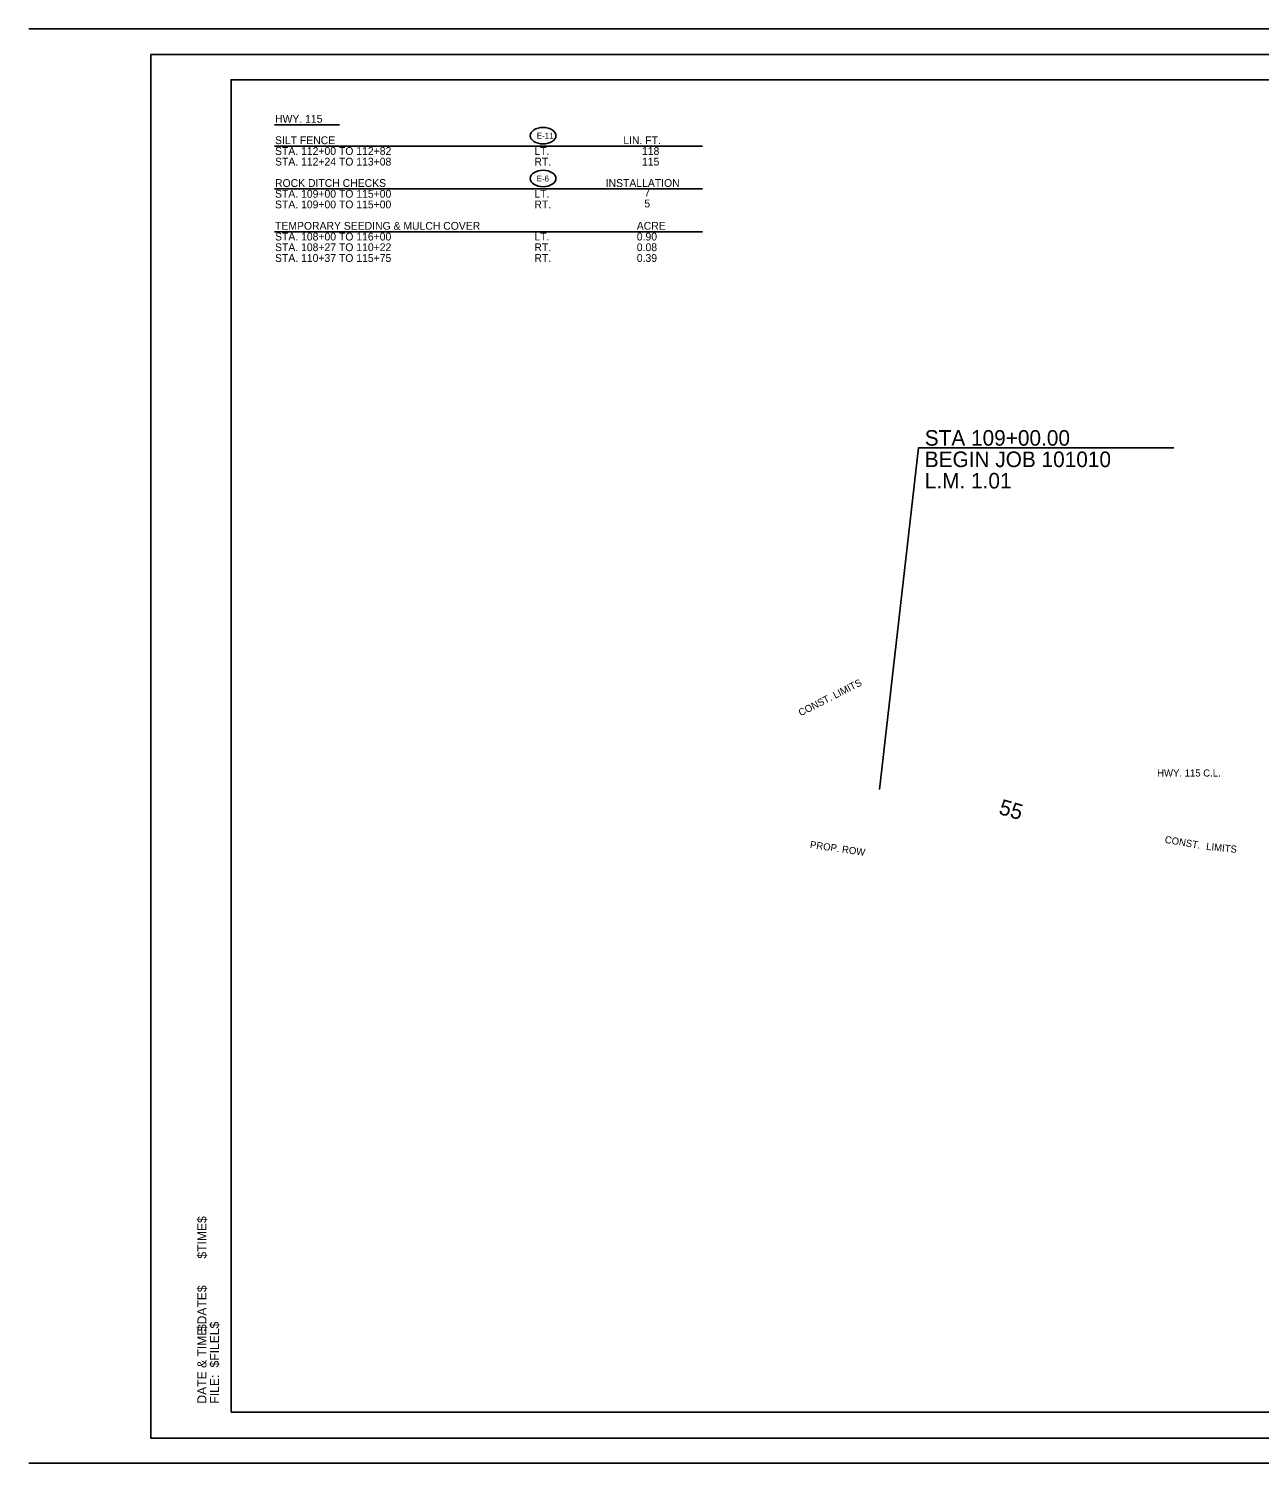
# Model space of a CAD drawing. Extents: x 9844 to 14104, y 9961 to 11067.
# Drawn here: x 9844 to 10793, y 9961 to 11067 of the extents above; entities that cross this region are included whole.
import ezdxf

# ---------------------------------------------------------------- set-up
doc = ezdxf.new("R2010")
doc.units = 0
for name, color, linetype in [('Default', 7, 'Continuous'), ('R_Border', 7, 'Continuous'), ('R_Detour Annot', 7, 'Continuous'), ('R_Erosion', 7, 'Continuous'), ('R_No Plot', 7, 'Continuous'), ('R_NoPlot', 7, 'Continuous'), ('R_Proposed Const Limits Annot', 7, 'Continuous'), ('R_ROW Annot Labels Ends', 7, 'Continuous'), ('STA Text', 7, 'Continuous'), ('TEXT', 7, 'Continuous')]:
    doc.layers.add(name, color=color, linetype=linetype)

msp = doc.modelspace()

# ---------------------------------------------------------------- linework, layer by layer
at = {"layer": 'R_Border'}
for p, q in [((11603.9, 11066.7), (9843.9, 11066.7)), ((10000, 11027.3), (11580.9, 11027.3)), ((10000, 10000), (10000, 11027.3)), ((10762.6, 11026), (10762.6, 11026)), ((10762.6, 11026), (10762.6, 11026)), ((11580.9, 10000), (10000, 10000)), ((9843.9, 9960.6), (11603.9, 9960.6))]:
    msp.add_line(p, q, dxfattribs=at)
at = {"layer": 'R_Erosion'}
for p, q in [((10033.6, 10992.7), (10083.6, 10992.7)), ((10033.6, 10976.2), (10363.6, 10976.2)), ((10033.6, 10943.2), (10363.6, 10943.2)), ((10033.6, 10910.2), (10363.6, 10910.2))]:
    msp.add_line(p, q, dxfattribs=at)
for centre in [(10240.6, 10984.2), (10240.6, 10951.2)]:
    msp.add_ellipse(centre, major_axis=(9.94, 0), ratio=0.638788, dxfattribs=at)
at = {"layer": 'R_No Plot'}
msp.add_lwpolyline([(10000, 10000), (11580.9, 10000), (11580.3, 10963.3), (11365.4, 10963.3), (11357.3, 10959.9), (11348.5, 10961.4), (11348.3, 10977.9), (11169.6, 10977.9), (11169.6, 11027.3), (10000, 11027.3)], close=True, dxfattribs=at)
msp.add_lwpolyline([(10000, 10000), (11580.9, 10000), (11580.3, 10963.3), (11365.4, 10963.3), (11357.3, 10959.9), (11348.5, 10961.4), (11348.3, 10977.9), (11169.6, 10977.9), (11169.6, 11027.3), (10000, 11027.3)], close=True, dxfattribs=at)
at = {"layer": 'R_NoPlot'}
msp.add_lwpolyline([(9938, 11046.8), (11604.7, 11046.8), (11604.7, 9980.1), (9938, 9980.1)], close=True, dxfattribs=at)
at = {"layer": 'STA Text'}
msp.add_lwpolyline([(10727.2, 10743.6), (10530.2, 10743.6), (10500, 10480)], dxfattribs=at)

# ---------------------------------------------------------------- texts
at = {"layer": 'Default'}
for s, height, p in [('$TIME$', 6.98, (9981, 10118.4)), ('$DATE$', 6.98, (9981, 10062.5)), ('DATE & TIME:', 6.984, (9981, 10006.6)), ('$FILEL$', 6.98, (9990.6, 10034.5)), ('FILE: ', 6.98, (9990.6, 10006.6))]:
    msp.add_text(s, height=height, rotation=90, dxfattribs=at).set_placement(p)
at = {"layer": 'R_Detour Annot'}
msp.add_text('55', height=12, rotation=343.9098, dxfattribs=at).set_placement((10591.4, 10461.4))
at = {"layer": 'R_Erosion'}
for s, height, p in [('HWY. 115', 6, (10033.9, 10994.2)), ('SILT FENCE', 6, (10033.9, 10977.7)), ('E-11', 4.54, (10235.8, 10981.9)), ('LIN. FT.', 6, (10302.5, 10977.7)), ('STA. 112+00 TO 112+82', 6, (10033.9, 10969.4)), ('LT.', 6, (10233.9, 10969.4)), ('118', 6, (10316.9, 10969.4)), ('STA. 112+24 TO 113+08', 6, (10033.9, 10961.2)), ('RT.', 6, (10233.9, 10961.2)), ('115', 6, (10316.9, 10961.2)), ('ROCK DITCH CHECKS   ', 6, (10033.9, 10944.7)), ('INSTALLATION', 6, (10288.9, 10944.7)), ('STA. 109+00 TO 115+00', 6, (10033.9, 10936.4)), ('LT.', 6, (10233.9, 10936.4)), ('7', 6, (10318.7, 10937.2)), ('STA. 109+00 TO 115+00', 6, (10033.9, 10928.2)), ('RT.', 6, (10233.9, 10928.2)), ('5', 6, (10318.7, 10928.9)), ('TEMPORARY SEEDING & MULCH COVER', 6, (10033.9, 10911.7)), ('ACRE', 6, (10312.9, 10911.7)), ('STA. 108+00 TO 116+00', 6, (10033.9, 10903.4)), ('LT.', 6, (10233.9, 10903.4)), ('0.90', 6, (10312.9, 10903.4)), ('STA. 108+27 TO 110+22', 6, (10033.9, 10895.2)), ('RT.', 6, (10233.9, 10895.2)), ('0.08', 6, (10312.9, 10895.2)), ('STA. 110+37 TO 115+75', 6, (10033.9, 10886.9)), ('RT.', 6, (10233.9, 10886.9)), ('0.39', 6, (10312.9, 10886.9))]:
    msp.add_text(s, height=height, dxfattribs=at).set_placement(p)
msp.add_text('E-6', height=4.54, rotation=360, dxfattribs=at).set_placement((10235.7, 10948.9))
at = {"layer": 'R_Proposed Const Limits Annot'}
for s, rotation, p in [('CONST. LIMITS', 26.9076, (10439.3, 10536.5)), ('CONST. ', 350.4049, (10719.8, 10439)), (' LIMITS', 354.2221, (10749.8, 10433.8))]:
    msp.add_text(s, height=5.5, rotation=rotation, dxfattribs=at).set_placement(p)
at = {"layer": 'R_ROW Annot Labels Ends'}
msp.add_text('PROP. ROW', height=5.5, rotation=351.6757, dxfattribs=at).set_placement((10446.2, 10435.1))
at = {"layer": 'STA Text'}
for s, p in [('STA 109+00.00', (10535, 10745.2)), ('BEGIN JOB 101010', (10535, 10728.7)), ('L.M. 1.01', (10535, 10712.2))]:
    msp.add_text(s, height=12, dxfattribs=at).set_placement(p)
at = {"layer": 'TEXT'}
msp.add_text('HWY. 115 C.L.', height=5.5, dxfattribs=at).set_placement((10714.2, 10490.1))

doc.saveas('drawing.dxf')
